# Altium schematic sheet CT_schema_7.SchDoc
size 254 x 194 mm
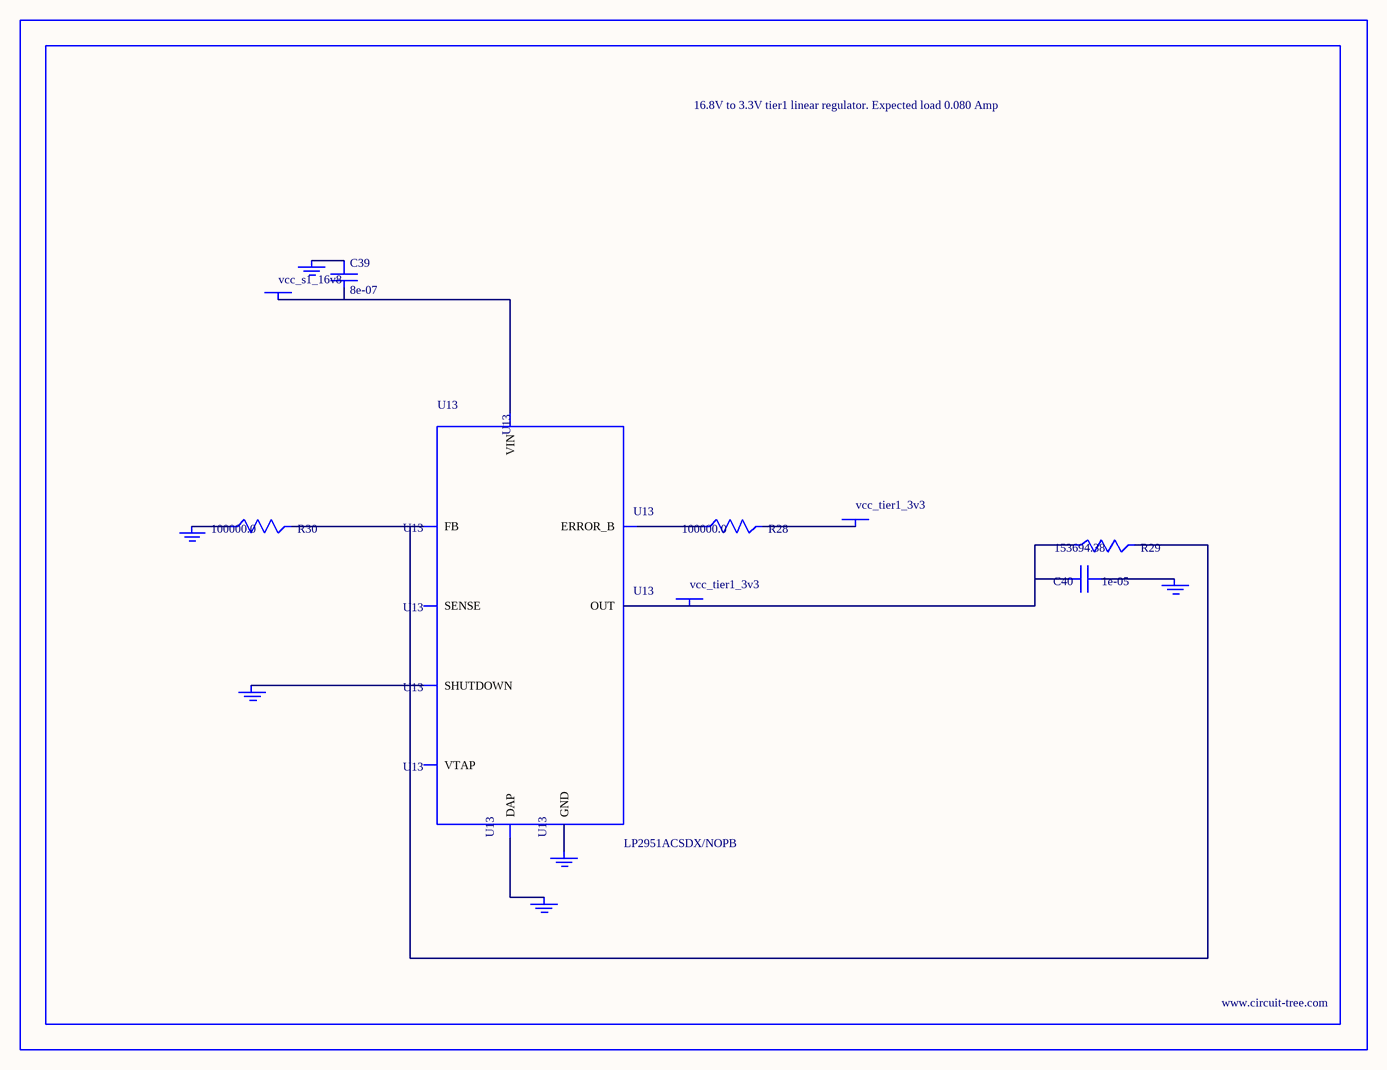
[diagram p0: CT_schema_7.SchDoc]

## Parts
BORDER6  (no value)
C39  8e-07  [R0603]
C40  1e-05  [C1210]
GND_INSTANCE_6_0  (no value)
GND_INSTANCE_6_1  (no value)
GND_INSTANCE_6_2  (no value)
GND_INSTANCE_6_3  (no value)
GND_INSTANCE_6_4  (no value)
GND_INSTANCE_6_5  (no value)
POWER_INSTANCE_6_0  vcc_tier1_3v3
POWER_INSTANCE_6_1  vcc_s1_16v8
POWER_INSTANCE_6_2  vcc_tier1_3v3
R28  100000.0  [R0603]
R29  153694.38  [R0603]
R30  100000.0  [R0603]
U13  LP2951ACSDX/NOPB  [WSON-8]

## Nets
NetC39_1: C39.1 GND_INSTANCE_6_3.0(GND)
NetC39_2: C39.2 POWER_INSTANCE_6_1.0(PWR) U13.8(VIN)
NetC40_1: C40.1 GND_INSTANCE_6_0.0(GND)
NetC40_2: C40.2 POWER_INSTANCE_6_2.0(PWR) R29.1 U13.1(OUT)
NetGND_INSTANCE_6_1_0: GND_INSTANCE_6_1.0(GND) U13.3(SHUTDOWN)
NetGND_INSTANCE_6_2_0: GND_INSTANCE_6_2.0(GND) R30.1
NetGND_INSTANCE_6_4_0: GND_INSTANCE_6_4.0(GND) U13.PAD(DAP)
NetGND_INSTANCE_6_5_0: GND_INSTANCE_6_5.0(GND) U13.4(GND)
NetPOWER_INSTANCE_6_0_0: POWER_INSTANCE_6_0.0(PWR) R28.2
NetR28_1: R28.1 U13.5(ERROR_B)
NetR29_2: R29.2 R30.2 U13.7(FB)

Not connected (* = marked no-connect by the designer): U13 2(SENSE) 6(VTAP)

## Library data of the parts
BORDER6 = BORDER_PAGE6
C39 = C39
C40 = GRM32DR61E106MA12L
GND_INSTANCE_6_0-GND_INSTANCE_6_5 = GND
POWER_INSTANCE_6_0-POWER_INSTANCE_6_2 = PWR
R28 R30 = RC0603JR-07100KL
R29 = R29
